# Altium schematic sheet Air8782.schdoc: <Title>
size 419 x 266 mm; Name: SIZEB; Symbol: SIZEB; Device: SIZEB; Drawn By: <Drawn By>; Checked By: <Checked By>; QC By: <QC By>; Released By: <Released By>; Drawn Date: <Drawn Date>; Checked Date: <Checked Date>; QC Date: <QC Date>; Release Date: <Release Date>; Company Name: <Company Name>; Code: <Code>; Sheet Size: B; Drawing Number: <Drawing Number>; Revision: <Revision>; Scale: <Scale>; Sheet Number: 1; Number of Sheets: 1; @Page No: 1; @Page Count: 1; @Schematic Name: _Air8782; @Project Name: Air8782; @Board Name: _Air8782; @Update Date: 2026-08-17; @Create Time: 11:33:07; @Update Time: 19:33:07; @Page Name: sheet1; @Create Date: 2026-08-17
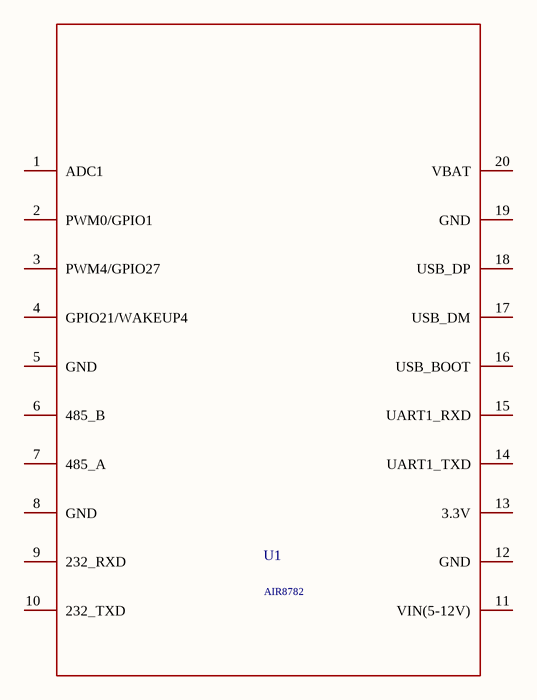
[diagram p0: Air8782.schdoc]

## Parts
U1  AIR8782

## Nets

Not connected (* = marked no-connect by the designer): U1 1(ADC1) 2(PWM0/GPIO1) 3(PWM4/GPIO27) 4(GPIO21/WAKEUP4) 5(GND) 6(485_B) 7(485_A) 8(GND) 9(232_RXD) 10(232_TXD) 11(VIN(5-12V)) 12(GND) 13(3.3V) 14(UART1_TXD) 15(UART1_RXD) 16(USB_BOOT) 17(USB_DM) 18(USB_DP) 19(GND) 20(VBAT)

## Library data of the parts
U1 = AIR8782: Add into BOM: yes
